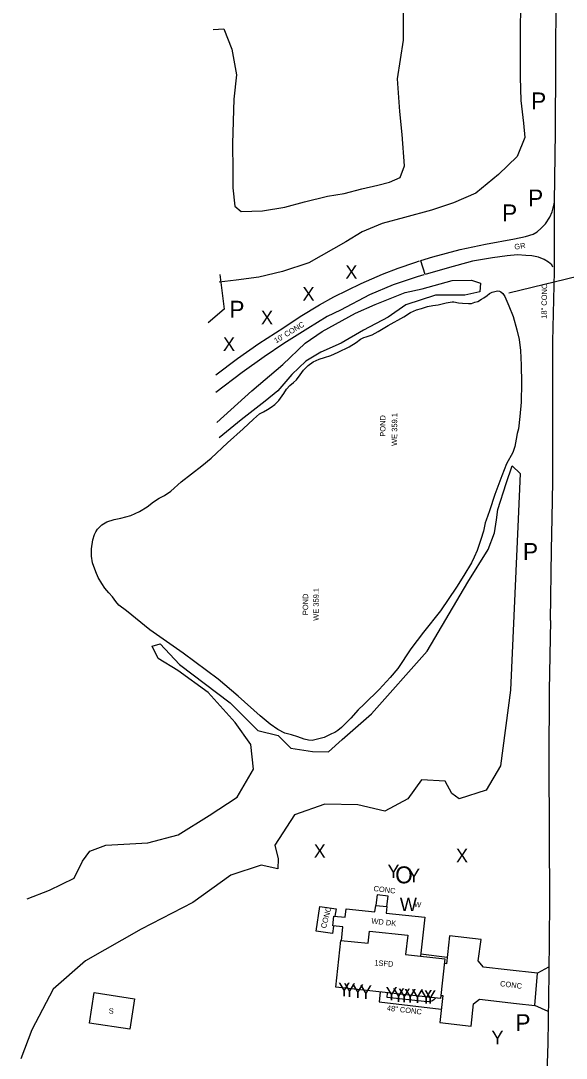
# Model space of a CAD drawing. Extents: x 2030130 to 2036320, y 723205 to 762423.
# Drawn here: x 2030882 to 2031285, y 727451 to 728217 of the extents above; entities that cross this region are included whole.
import ezdxf

# ---------------------------------------------------------------- set-up
doc = ezdxf.new("R2010")
doc.units = 0
for name, color, linetype in [('Draft_Station Cardinal Points', 7, 'Continuous'), ('Draft_Station Labels Major', 7, 'Continuous'), ('Draft_Station Tics Major', 7, 'Continuous'), ('Draft_Station Tics Minor', 7, 'Continuous'), ('Exist Terrain Model Ground Surface', 7, 'Continuous'), ('Old_Level_23', 7, 'Continuous'), ('Old_Level_26', 7, 'Continuous'), ('Old_Level_28', 7, 'Continuous'), ('Prop Alignment Horizontal', 7, 'Continuous'), ('Prop Alignment Vertical', 7, 'Continuous'), ('Prop Horizontal Alignment Ramp', 7, 'Continuous')]:
    doc.layers.add(name, color=color, linetype=linetype)

msp = doc.modelspace()

# ---------------------------------------------------------------- linework, layer by layer
at = {"layer": 'Draft_Station Labels Major'}
for p, q in [((2031180.53, 728029.84), (2031177.25, 728039.81)), ((2031272.99, 727774.55), (2031271.81, 727722.76))]:
    msp.add_line(p, q, dxfattribs=at)
for points in [[(2031274.1, 727850.02), (2031274.7, 727877.12), (2031274.54, 727929.23), (2031274.69, 727980.31), (2031275.85, 728031.88), (2031275.79, 728083.45), (2031276.57, 728134.69), (2031276.91, 728185.69), (2031277.1, 728237.55), (2031277.45, 728288.61), (2031278.77, 728342.05), (2031280.83, 728391.92), (2031282.52, 728442.43)], [(2031177.2, 728040.05), (2031186.19, 728042.91), (2031206.35, 728048.17), (2031224.94, 728052.06), (2031246.34, 728056.03), (2031254.56, 728057.77), (2031260.11, 728059.63), (2031263.1, 728061.21), (2031265.9, 728063.91), (2031269.27, 728067.26), (2031272.32, 728072.04), (2031274.06, 728075.9), (2031275.53, 728081.85), (2031275.59, 728082.45)], [(2031274.64, 728035.24), (2031273.75, 728036.78), (2031271.52, 728038.92), (2031268.31, 728040.8), (2031263.92, 728042.54), (2031259.21, 728043.43), (2031254.64, 728043.86), (2031248.63, 728044.22), (2031240.99, 728043.59), (2031230.09, 728042.1), (2031215.34, 728039.54), (2031196.76, 728034.41), (2031180.42, 728029.7)], [(2031025.92, 727955.7), (2031041.93, 727967.87), (2031057.8, 727978.86), (2031076.22, 727990.72), (2031088.13, 727998.82), (2031102.52, 728007.45), (2031113.14, 728013.25), (2031133.2, 728023.03), (2031148.84, 728030.04), (2031160.38, 728034.41), (2031172.83, 728038.65), (2031176.28, 728039.75)], [(2031179.4, 728029.41), (2031174.58, 728028.02), (2031156.91, 728022.04), (2031139.25, 728014.64), (2031117.89, 728003.35), (2031108.18, 727998.66), (2031093.8, 727989.9), (2031076.16, 727978.77), (2031061.58, 727968.89), (2031045.31, 727957.44), (2031025.86, 727942.7)], [(2031272.99, 727774.55), (2031273.58, 727826.61), (2031274.1, 727850.02)], [(2031271.81, 727722.76), (2031271.54, 727670.95), (2031271.98, 727617.05), (2031272.17, 727566.07), (2031271.57, 727513.89), (2031270.8, 727462.29), (2031269.09, 727411.4), (2031266.76, 727360.17), (2031267.41, 727307.86), (2031267.22, 727254.5), (2031266.37, 727203.11), (2031265.79, 727153.75), (2031265.27, 727099.78), (2031264.12, 727048.66), (2031262.61, 726996.01), (2031261.43, 726946.21)], [(2031223.4, 727518.73), (2031219.59, 727523.32), (2031221.62, 727538.99), (2031198.28, 727541.68), (2031196.16, 727521.18), (2031194.33, 727521.42)], [(2031191.75, 727497.82), (2031193.41, 727497.64), (2031191.22, 727477.74), (2031214.3, 727475.25), (2031216.06, 727491.52), (2031220.52, 727494.99), (2031247.83, 727491.95), (2031261.38, 727490.49), (2031263.2, 727514.22)], [(2031263.2, 727514.22), (2031240.99, 727516.79), (2031223.4, 727518.73)], [(2031271.53, 727518.68), (2031263.2, 727514.22)], [(2031271.1, 727485.86), (2031261.38, 727490.49)]]:
    msp.add_lwpolyline(points, dxfattribs=at)
at = {"layer": 'Draft_Station Tics Major'}
for points in [[(2031206.59, 728453.19), (2031221.28, 728469.6), (2031240.31, 728469.71), (2031248.08, 728451.73), (2031251.95, 728423.17), (2031248.15, 728389.88), (2031244.91, 728374.27), (2031246.53, 728356.25), (2031250.16, 728338.75), (2031250.31, 728311.6), (2031250.46, 728283.61), (2031250.72, 728235.61), (2031250.63, 728202.34), (2031250.44, 728175.37)], [(2031160.08, 728174.16), (2031164.33, 728202.74), (2031164.15, 728251.15), (2031178.23, 728263.68), (2031208.49, 728279.44), (2031219.3, 728289.44), (2031228.01, 728313.69), (2031229.01, 728334.8), (2031227.98, 728344.93), (2031215.6, 728354.73), (2031208.94, 728361.5), (2031201.3, 728378.98), (2031196.47, 728394.5), (2031196.03, 728411.67), (2031195.95, 728426.61), (2031201.27, 728443.63), (2031206.59, 728453.19)], [(2031024.04, 728210.65), (2031031.82, 728211.09), (2031037.77, 728196.07), (2031041.27, 728177.06), (2031039.21, 728159.18)], [(2031250.44, 728175.37), (2031250.99, 728158.14), (2031252.92, 728141.51), (2031254.03, 728130.73), (2031248.32, 728116.89), (2031234.58, 728103.53), (2031217.75, 728089.83), (2031201.28, 728082.57), (2031185, 728077.29), (2031165.23, 728071.85), (2031148.81, 728067.29), (2031133.85, 728061.36), (2031121.98, 728053.93), (2031094.51, 728038.39), (2031075.21, 728031.91), (2031057.8, 728027.8), (2031040.97, 728025.61), (2031028.42, 728024.03)], [(2031039.21, 728159.18), (2031038.26, 728126.42), (2031038.5, 728106.16), (2031038.57, 728093.6), (2031039.89, 728080.26), (2031044.58, 728076.27), (2031060.43, 728076.75), (2031076.86, 728079.47), (2031091.37, 728083.36), (2031108.45, 728087.6), (2031120.61, 728089.44), (2031133.68, 728093.06), (2031145.5, 728095.62), (2031154.04, 728097.84), (2031161.98, 728101.3), (2031165.09, 728109.87), (2031163.45, 728133.08), (2031161.85, 728150.04), (2031160.08, 728174.16)], [(2031026.61, 727920.56), (2031052.53, 727943.85), (2031075.51, 727963.44), (2031091.8, 727979.05), (2031104.51, 727987.67), (2031128.92, 728001.25), (2031143.44, 728007.7), (2031165.58, 728016.45), (2031178.26, 728019.22), (2031200.4, 728025.41), (2031214.54, 728025.55), (2031221.13, 728023.35), (2031220.84, 728016.97), (2031209.6, 728014.48), (2031188.14, 728014.5), (2031166.14, 728007.48), (2031153.13, 727998.32), (2031134.83, 727988.62), (2031118.37, 727979), (2031103.41, 727972.54), (2031092.27, 727965.7), (2031082.12, 727955.98), (2031071.73, 727944.02), (2031062.37, 727936.34), (2031044.75, 727922.57), (2031028.31, 727909.32)], [(2031232.93, 727848.79), (2031234.08, 727856.43), (2031240.25, 727875.67), (2031244.63, 727888.55), (2031250.5, 727883.05), (2031248.98, 727849.27)], [(2031248.98, 727849.27), (2031243.28, 727723.11), (2031236, 727667.32), (2031225.46, 727649.22), (2031205.4, 727642.81), (2031200.07, 727646.86), (2031195.09, 727655.82), (2031177.74, 727656.84), (2031167.68, 727642.85), (2031150.7, 727633.69), (2031130.8, 727638.4), (2031106.44, 727638.96), (2031083.89, 727631.07), (2031069.41, 727608.7), (2031072.02, 727598.67), (2031071.69, 727591.12), (2031059.49, 727593.92), (2031037.06, 727586.56), (2031008.93, 727566.44), (2030970.87, 727546.62), (2030929.93, 727523.34), (2030905.91, 727502.47), (2030890.18, 727472.54), (2030882.04, 727451.02)], [(2030886.88, 727569.12), (2030903.36, 727575.5), (2030921.41, 727584.27), (2030927.64, 727596.9), (2030933.13, 727604.23), (2030944.87, 727608.58), (2030975.82, 727610.33), (2030998.13, 727616.36), (2031021.16, 727630.48), (2031041.81, 727644.17), (2031053.79, 727664.67), (2031051.89, 727683.05), (2031040.36, 727699.22), (2031020.3, 727721.26), (2030997.91, 727737.46), (2030983.4, 727746.32), (2030978.95, 727755.41), (2030985.02, 727757.19), (2030999.06, 727742.05), (2031036.59, 727713.63), (2031057.03, 727693.31), (2031071.95, 727689.72), (2031081.24, 727680.3), (2031097.19, 727677.69), (2031109.11, 727677.67), (2031119.22, 727686.73), (2031140.88, 727705.59), (2031182, 727751.91), (2031211.83, 727802.75), (2031226.95, 727826.84), (2031231.47, 727839.06), (2031232.93, 727848.79)]]:
    msp.add_lwpolyline(points, dxfattribs=at)
at = {"layer": 'Draft_Station Tics Minor'}
msp.add_line((2031312.69, 728033.06), (2031242.09, 728015.98), dxfattribs=at)
at = {"layer": 'Exist Terrain Model Ground Surface'}
for points in [[(2031028.93, 728029.72), (2031032.22, 728004.12), (2031020.27, 727994.18)], [(2031152.23, 727563.36), (2031153.09, 727571.04), (2031144.91, 727571.97), (2031144.08, 727564.4)], [(2031112.81, 727548.9), (2031112.04, 727543.62), (2031100, 727545.35), (2031102.63, 727563.49), (2031114.67, 727561.76), (2031113.87, 727556.23)], [(2031118.68, 727538.12), (2031119.77, 727548.33), (2031112.27, 727549.14), (2031113.1, 727556.41), (2031121.48, 727555.51), (2031122.17, 727561.81), (2031143.4, 727559.5), (2031143.92, 727564.29), (2031152.2, 727563.4), (2031151.67, 727558.52), (2031180.15, 727555.47), (2031177.08, 727526.78)], [(2031196.63, 727525.71), (2031177.22, 727528.23)], [(2031147.11, 727500.23), (2031146.45, 727493.04), (2031192.32, 727487.69)], [(2031188.14, 727495.88), (2031187.18, 727494.74), (2031185.74, 727493.87), (2031184.09, 727493.26), (2031182.51, 727493.18), (2031179.6, 727493.35), (2031152.29, 727496.4), (2031152.68, 727499.84)]]:
    msp.add_lwpolyline(points, dxfattribs=at)
for points in [[(2031139.3, 727545.33), (2031167.51, 727542.19), (2031165.94, 727528.06), (2031194.81, 727524.89), (2031191.66, 727495.65), (2031114.54, 727504), (2031118.31, 727538.43), (2031138.38, 727536.33)], [(2030936.2, 727499.88), (2030966.07, 727495.31), (2030962.64, 727472.88), (2030932.78, 727477.42)]]:
    msp.add_lwpolyline(points, close=True, dxfattribs=at)
at = {"layer": 'Prop Alignment Horizontal'}
for points in [[(2031208, 728008.58), (2031212.36, 728008.3), (2031214.67, 728008.45), (2031217.11, 728009.27), (2031219.35, 728009.82), (2031221.98, 728011.49), (2031223.69, 728012.57), (2031226.18, 728014.31), (2031227.89, 728015.78), (2031229.79, 728016.79), (2031231.77, 728017.34), (2031233.68, 728017.68), (2031235.21, 728017.37), (2031236.2, 728016.98), (2031237.8, 728015.74), (2031239.08, 728013.44), (2031242.12, 728006.53), (2031245.23, 727998.69), (2031248.16, 727989.01), (2031249.88, 727981.76), (2031250.75, 727973.64), (2031251.32, 727962.87), (2031251.57, 727949.79), (2031251.25, 727935.44)], [(2031106.14, 727968.63), (2031110.75, 727970.06), (2031116.15, 727972.43), (2031124.37, 727976.47), (2031129.63, 727979.56), (2031132.71, 727981.97), (2031135.15, 727983.38), (2031136.86, 727983.79), (2031141.21, 727985.29), (2031145.74, 727987.71), (2031153.1, 727992.07), (2031164.67, 727998.53), (2031169.6, 728001.68), (2031174.08, 728003.64), (2031177.63, 728004.73), (2031182.18, 728006.16), (2031186.14, 728006.86), (2031189.9, 728007.29), (2031193.06, 728008.18), (2031196.03, 728008.93), (2031200.39, 728009.64), (2031201.58, 728009.52), (2031204.89, 728008.89), (2031208, 728008.58)], [(2030937.56, 727839.92), (2030938.7, 727841.95), (2030941.77, 727845.15), (2030945.65, 727847.36), (2030951.05, 727848.87), (2030955.87, 727849.91), (2030963.38, 727851.96), (2030969.76, 727854.93), (2030975.42, 727858.22), (2030980.01, 727862.1), (2030984.28, 727864.71), (2030988.16, 727866.67), (2030992.75, 727870.01), (2031000.48, 727876.83), (2031015.57, 727888.6), (2031022.52, 727894.22), (2031034.58, 727905.57), (2031046.04, 727915.85), (2031053.84, 727923.13), (2031058.1, 727926.87), (2031061.19, 727928.49), (2031064.08, 727930.23), (2031066.84, 727931.84), (2031069.46, 727933.92), (2031072.48, 727936.79), (2031076.06, 727941.91), (2031078.21, 727945.1), (2031080.57, 727947.84), (2031083.39, 727950.04), (2031085.48, 727951.98), (2031088.16, 727955.64), (2031090.77, 727959.17), (2031094.17, 727962.64), (2031097.85, 727965.38), (2031102.12, 727967.4), (2031106.14, 727968.63)], [(2031251.25, 727935.44), (2031250.22, 727925.06), (2031249.32, 727915.8), (2031248.36, 727912.55), (2031247.47, 727908.31), (2031246.67, 727902.75), (2031245.12, 727898.31), (2031240.44, 727890.01), (2031237.09, 727881.12), (2031231.8, 727867.32), (2031227.82, 727855.26), (2031225.38, 727848.56)], [(2031225.38, 727848.56), (2031224.6, 727846.44), (2031223.34, 727840.35), (2031221.48, 727834.18), (2031218.71, 727826.09), (2031216.64, 727821.25), (2031214.5, 727817.07), (2031209.04, 727807.57), (2031203.64, 727799.12), (2031191.71, 727781.5), (2031179.1, 727765.85), (2031169.77, 727753.53), (2031160.33, 727739.1), (2031154.64, 727732.37), (2031146.6, 727723.44), (2031143.13, 727720.11), (2031139.06, 727716.37), (2031135.53, 727712.76), (2031131.01, 727708.56), (2031125.52, 727702.43), (2031121.72, 727698.49), (2031118.64, 727695.56), (2031115.89, 727693.22), (2031113.72, 727691.81), (2031111.35, 727690.79), (2031108.79, 727689.58), (2031105.83, 727688.03), (2031102.99, 727687.28), (2031099.96, 727686.59), (2031097.06, 727685.97), (2031094.28, 727686.14), (2031091.04, 727686.9), (2031086.53, 727688.58), (2031081.69, 727690.12), (2031076.85, 727691.26), (2031071.6, 727694.12), (2031066.15, 727698.03), (2031058.69, 727704.04), (2031042.56, 727718.56), (2031027.77, 727731.11), (2031001.75, 727750.29), (2030977.27, 727767.64), (2030959.95, 727781.55), (2030954.43, 727785.86), (2030952.22, 727788.54), (2030949.81, 727791.89), (2030946.94, 727794.97), (2030944.13, 727798.38), (2030941.85, 727801.86), (2030939.23, 727806.13), (2030937.41, 727810.48), (2030935.1, 727817), (2030934.26, 727821.95), (2030934.27, 727827.23), (2030935.14, 727833.92), (2030936.42, 727837.89), (2030937.56, 727839.92)]]:
    msp.add_lwpolyline(points, dxfattribs=at)

# ---------------------------------------------------------------- texts
at = {"layer": 'Draft_Station Cardinal Points'}
msp.add_text('O', height=12.5, dxfattribs=at).set_placement((2031158.29, 727580.53))
at = {"layer": 'Draft_Station Tics Major'}
for s, p in [('X', (2031121.51, 728026.59)), ('X', (2031089.89, 728010.44)), ('X', (2031059.27, 727992.98)), ('X', (2031031.23, 727973.43)), ('X', (2031098.16, 727599.37)), ('X', (2031203.14, 727596)), ('Y', (2031152.57, 727584.4)), ('Y', (2031167.68, 727581.24)), ('Y', (2031116.2, 727497.24)), ('Y', (2031120.18, 727496.75)), ('Y', (2031126.27, 727496.01)), ('Y', (2031132.24, 727495.14)), ('Y', (2031151.17, 727494.13)), ('Y', (2031156.34, 727492.99)), ('Y', (2031160.58, 727492.76)), ('Y', (2031164.95, 727492.54)), ('Y', (2031170.25, 727492.32)), ('Y', (2031176.74, 727491.72)), ('Y', (2031179.65, 727491.62)), ('Y', (2031229.3, 727461.78))]:
    msp.add_text(s, height=10, dxfattribs=at).set_placement(p)
at = {"layer": 'Exist Terrain Model Ground Surface'}
msp.add_text('W', height=10, dxfattribs=at).set_placement((2031161.73, 727560.01))
at = {"layer": 'Old_Level_23'}
for s, rotation, p in [('GR', 8.66852, (2031246.54, 728048.07)), ("10' CONC", 31.33907, (2031070.42, 727978.85)), ('CONC', 352.76281, (2031235.47, 727504.7))]:
    msp.add_text(s, height=4, rotation=rotation, dxfattribs=at).set_placement(p)
at = {"layer": 'Old_Level_26'}
msp.add_text('18" CONC', height=4, rotation=89.18178, dxfattribs=at).set_placement((2031270.05, 727997.07))
at = {"layer": 'Old_Level_28'}
for s, rotation, p in [('CONC', 353.28609, (2031142.15, 727574.83)), ('W', 352.60959, (2031172.02, 727563.21)), ('CONC', 75.23886, (2031107.17, 727546.93)), ('WD DK', 353.5132, (2031140.53, 727550.92)), ('1SFD', 355.60744, (2031142.78, 727519.98)), ('48" CONC', 353.43934, (2031151.97, 727486.64)), ('S', 356.13246, (2030946.81, 727484.47))]:
    msp.add_text(s, height=4, rotation=rotation, dxfattribs=at).set_placement(p)
at = {"layer": 'Prop Alignment Vertical'}
for s, p in [('POND', (2031151.09, 727910.05)), ('WE 359.1', (2031159.74, 727903.28)), ('WE 359.1', (2031101.85, 727774.25)), ('POND', (2031094.07, 727778.39))]:
    msp.add_text(s, height=4, rotation=89.84139, dxfattribs=at).set_placement(p)
at = {"layer": 'Prop Horizontal Alignment Ramp'}
for p in [(2031258.6, 728151.56), (2031256.36, 728079.96), (2031237.14, 728068.94), (2031035.96, 727997.86), (2031252.56, 727819.11), (2031246.97, 727471.48)]:
    msp.add_text('P', height=12.5, dxfattribs=at).set_placement(p)

doc.saveas('drawing.dxf')
